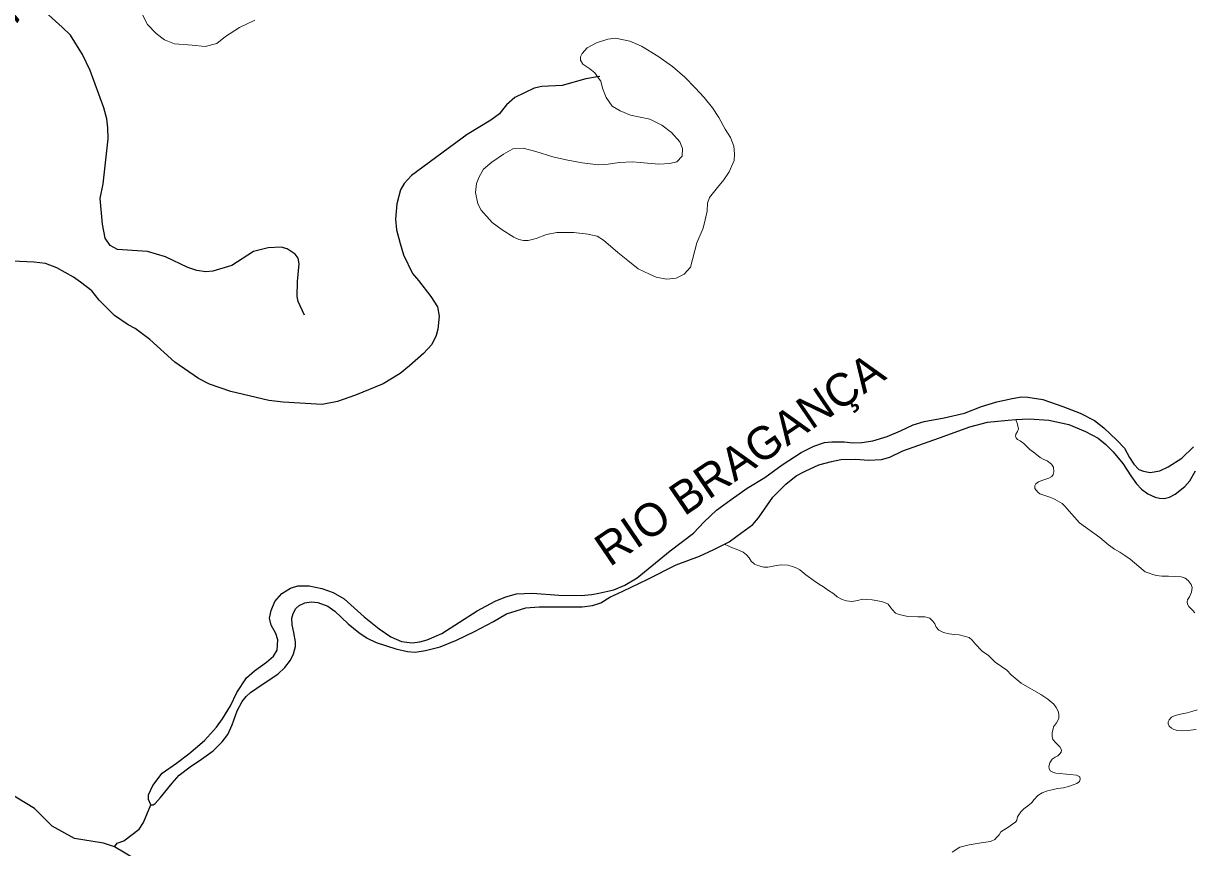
# Model space of a CAD drawing. Extents: x 267.7 to 296, y 7537.7 to 7565.8.
# Drawn here: x 278.742 to 282.305, y 7559.393 to 7561.905 of the extents above; entities that cross this region are included whole.
import ezdxf
from ezdxf.enums import TextEntityAlignment as Align

# ---------------------------------------------------------------- set-up
doc = ezdxf.new("R2010")
doc.units = 0
doc.header["$LTSCALE"] = 0.04
doc.linetypes.add('SHORT_DASHED', pattern=[2.7, 1.5, -1.2])
for name, color, linetype, lineweight in [('2', 7, 'Continuous', 25), ('21', 7, 'SHORT_DASHED', 13), ('7', 7, 'Continuous', 25)]:
    doc.layers.add(name, color=color, linetype=linetype, lineweight=lineweight)
doc.layers.add('61', color=7, linetype='Continuous')

msp = doc.modelspace()

# ---------------------------------------------------------------- linework, layer by layer
at = {"layer": '2'}
for points in [[(279.1303, 7559.5233), (279.1236, 7559.5397), (279.1236, 7559.5541), (279.1365, 7559.5828), (279.1646, 7559.6202), (279.2084, 7559.6504), (279.2458, 7559.6792), (279.294, 7559.7195), (279.3306, 7559.7597), (279.3486, 7559.7856), (279.3731, 7559.8251), (279.3925, 7559.8661), (279.422, 7559.9107), (279.4464, 7559.9323), (279.4824, 7559.9582), (279.5046, 7559.9761), (279.5154, 7559.9948), (279.5176, 7560.0265), (279.5111, 7560.0459), (279.4975, 7560.071), (279.4924, 7560.0926), (279.4967, 7560.1156), (279.5082, 7560.1429), (279.5298, 7560.1674), (279.5564, 7560.1839), (279.578, 7560.1904), (279.6132, 7560.1904), (279.6513, 7560.1832), (279.6858, 7560.1703), (279.7196, 7560.1516), (279.78, 7560.0962), (279.826, 7560.0595), (279.862, 7560.0358), (279.8943, 7560.0214), (279.9267, 7560.0171), (279.9497, 7560.02), (279.972, 7560.0265), (280.0166, 7560.0452), (280.1251, 7560.1142), (280.1791, 7560.1437), (280.2121, 7560.1573), (280.2445, 7560.1667), (280.2934, 7560.1681), (280.3732, 7560.1624), (280.4415, 7560.1616), (280.4739, 7560.1645), (280.4954, 7560.1681), (280.5407, 7560.1789), (280.5745, 7560.1926), (280.6119, 7560.2156), (280.7126, 7560.2975), (280.7838, 7560.3515), (280.8168, 7560.386), (280.8542, 7560.4219), (280.8988, 7560.4536), (280.9477, 7560.4881), (281.0016, 7560.5211), (281.0541, 7560.5592), (281.1116, 7560.5974), (281.1504, 7560.6168), (281.1835, 7560.6276), (281.2051, 7560.6297), (281.2425, 7560.6297), (281.2698, 7560.6268), (281.2964, 7560.6276), (281.3302, 7560.6326), (281.3741, 7560.6462), (281.4143, 7560.6628), (281.4531, 7560.6815), (281.4869, 7560.6915), (281.5473, 7560.7023), (281.6099, 7560.7174), (281.6617, 7560.7368), (281.7084, 7560.7512), (281.7551, 7560.7613), (281.7832, 7560.7663), (281.8026, 7560.7656), (281.8479, 7560.7584), (281.9097, 7560.7368), (281.9622, 7560.7167), (282.0061, 7560.6951), (282.0341, 7560.6721), (282.0736, 7560.6347), (282.0974, 7560.6103), (282.1125, 7560.5823), (282.1254, 7560.5614), (282.1412, 7560.5456), (282.1549, 7560.5398), (282.175, 7560.5362), (282.2052, 7560.5413), (282.2304, 7560.5535), (282.2721, 7560.5801), (282.3073, 7560.6146)], [(280.8785, 7560.3178), (280.893, 7560.3249), (280.9311, 7560.3529), (280.9642, 7560.3781), (280.9822, 7560.3982), (281.0261, 7560.4607), (281.0649, 7560.5003), (281.0972, 7560.5262), (281.1238, 7560.5406), (281.1663, 7560.56), (281.2044, 7560.57), (281.2324, 7560.5758), (281.2784, 7560.5772), (281.3173, 7560.5736), (281.3568, 7560.5758), (281.382, 7560.583), (281.4222, 7560.6017), (281.533, 7560.6419), (281.6257, 7560.675), (281.6796, 7560.6894), (281.7429, 7560.6959), (281.7662, 7560.6974)], [(281.7662, 7560.6974), (281.8069, 7560.7002), (281.8666, 7560.6959), (281.9277, 7560.6829), (281.978, 7560.6613), (282.0168, 7560.6405), (282.0406, 7560.6218), (282.0629, 7560.5988), (282.0916, 7560.5636), (282.1161, 7560.5262), (282.134, 7560.5017), (282.1491, 7560.4852), (282.1678, 7560.4715), (282.1901, 7560.4615), (282.2038, 7560.4579), (282.2182, 7560.4571), (282.234, 7560.4615), (282.252, 7560.4701), (282.2807, 7560.4938), (282.2958, 7560.5111), (282.3138, 7560.5413)], [(279.1303, 7559.5233), (279.1372, 7559.5232), (279.1437, 7559.5275), (279.1602, 7559.5462), (279.1955, 7559.59), (279.217, 7559.6138), (279.2501, 7559.6396), (279.2846, 7559.6627), (279.3206, 7559.6885), (279.3479, 7559.7151), (279.3652, 7559.7381), (279.3781, 7559.7669), (279.3939, 7559.81), (279.409, 7559.8381), (279.4205, 7559.8539), (279.4342, 7559.8661), (279.4723, 7559.892), (279.5169, 7559.9215), (279.5392, 7559.9416), (279.5564, 7559.9646), (279.565, 7559.984), (279.5708, 7560.0056), (279.5708, 7560.0207), (279.5658, 7560.0488), (279.5607, 7560.0718), (279.56, 7560.0919), (279.5643, 7560.107), (279.5722, 7560.1221), (279.5823, 7560.1307), (279.5996, 7560.1386), (279.619, 7560.1422), (279.6391, 7560.1401), (279.67, 7560.1286), (279.6909, 7560.1135), (279.7319, 7560.0754), (279.7642, 7560.0488), (279.7894, 7560.0315), (279.8167, 7560.0186), (279.8771, 7559.9984), (279.9123, 7559.9905), (279.936, 7559.9891), (279.967, 7559.9934), (280.0123, 7560.0049), (280.0619, 7560.0257), (280.1165, 7560.0516), (280.1748, 7560.0818), (280.2143, 7560.1056), (280.2438, 7560.1142), (280.2733, 7560.1235), (280.3135, 7560.1271), (280.4444, 7560.1264), (280.476, 7560.1307), (280.5019, 7560.1386), (280.5292, 7560.1559), (280.5681, 7560.1746), (280.645, 7560.2112), (280.7313, 7560.2544), (280.8017, 7560.281), (280.8456, 7560.3018), (280.8785, 7560.3178)]]:
    msp.add_lwpolyline(points, dxfattribs=at)
at = {"layer": '21'}
for points in [[(279.0976, 7561.9448), (279.12, 7561.9018), (279.1463, 7561.8737), (279.1725, 7561.855), (279.2024, 7561.8419), (279.2567, 7561.8381), (279.296, 7561.8344), (279.3316, 7561.8437), (279.3578, 7561.8643), (279.4009, 7561.8924), (279.4477, 7561.9149)], [(280.4918, 7561.7422), (280.4833, 7561.754), (280.4676, 7561.7661), (280.4471, 7561.7806), (280.4398, 7561.7927), (280.4398, 7561.8024), (280.4446, 7561.8132), (280.4603, 7561.8301), (280.4881, 7561.8459), (280.5232, 7561.8567), (280.5461, 7561.8592), (280.5896, 7561.8507), (280.6259, 7561.835), (280.6754, 7561.8048), (280.7202, 7561.7734), (280.7576, 7561.7407), (280.789, 7561.7081), (280.8168, 7561.6791), (280.8422, 7561.6477), (280.8616, 7561.6175), (280.8809, 7561.5824), (280.8966, 7561.557), (280.9063, 7561.5304), (280.9087, 7561.5075), (280.9075, 7561.4869), (280.893, 7561.4519), (280.8761, 7561.4277), (280.8567, 7561.4048), (280.8325, 7561.3746), (280.8265, 7561.3564), (280.8253, 7561.3323), (280.8193, 7561.3057), (280.8132, 7561.2803), (280.7939, 7561.2356), (280.7745, 7561.1619), (280.7552, 7561.1401), (280.731, 7561.128), (280.702, 7561.1256), (280.6706, 7561.1317), (280.6501, 7561.1401), (280.615, 7561.157), (280.5836, 7561.1824), (280.5534, 7561.2066), (280.5099, 7561.244), (280.4906, 7561.2561), (280.4616, 7561.2622), (280.4193, 7561.267), (280.3673, 7561.267), (280.3359, 7561.261), (280.3045, 7561.2489), (280.2803, 7561.2428), (280.2658, 7561.2428), (280.2513, 7561.2465), (280.2368, 7561.2537)], [(280.2368, 7561.2537), (280.2005, 7561.2755), (280.1703, 7561.2984), (280.1365, 7561.3359), (280.1268, 7561.3552), (280.1196, 7561.3891), (280.1232, 7561.4169), (280.1304, 7561.4374), (280.1437, 7561.4604), (280.1691, 7561.4821), (280.2054, 7561.5063), (280.2332, 7561.522), (280.2646, 7561.5244), (280.3032, 7561.5147), (280.3552, 7561.4978), (280.3963, 7561.4894), (280.4446, 7561.4797), (280.493, 7561.4737), (280.5244, 7561.4761), (280.5582, 7561.4809), (280.5981, 7561.4833), (280.6211, 7561.4809), (280.6779, 7561.4761), (280.7117, 7561.4773), (280.7335, 7561.4833), (280.7492, 7561.5002), (280.7504, 7561.5232), (280.7419, 7561.5437), (280.7165, 7561.5727), (280.6875, 7561.5945), (280.6513, 7561.6126), (280.5921, 7561.6247), (280.5606, 7561.638), (280.5365, 7561.6525), (280.5183, 7561.6791), (280.5063, 7561.7069), (280.5014, 7561.7286), (280.4918, 7561.7422)], [(282.2913, 7560.2074), (282.2822, 7560.2143), (282.2696, 7560.2183), (282.2313, 7560.22), (282.2113, 7560.2206), (282.1948, 7560.2223), (282.1833, 7560.2251), (282.1719, 7560.2291), (282.1605, 7560.2337), (282.1536, 7560.2388), (282.1142, 7560.272), (282.0982, 7560.2834), (282.0834, 7560.2937), (282.0668, 7560.3028), (282.0485, 7560.3159), (282.0217, 7560.3382), (281.96, 7560.3833), (281.9446, 7560.4005), (281.9286, 7560.4188), (281.916, 7560.433), (281.9069, 7560.4416), (281.8863, 7560.4536), (281.8726, 7560.4605), (281.8549, 7560.4662), (281.8395, 7560.4713), (281.8326, 7560.4765), (281.8235, 7560.4873), (281.824, 7560.4959), (281.8269, 7560.5016), (281.8355, 7560.5079), (281.8486, 7560.513), (281.8663, 7560.5187), (281.876, 7560.5244), (281.88, 7560.5296), (281.8823, 7560.5387), (281.8806, 7560.5524), (281.8743, 7560.5616), (281.8617, 7560.5719), (281.8497, 7560.577), (281.84, 7560.5821), (281.824, 7560.5947), (281.8086, 7560.6067), (281.7909, 7560.6244), (281.7795, 7560.6324), (281.7709, 7560.637), (281.7669, 7560.6415), (281.7652, 7560.6455), (281.7663, 7560.653), (281.7715, 7560.6615), (281.7738, 7560.669), (281.7732, 7560.6741), (281.7715, 7560.681), (281.7709, 7560.6838), (281.7662, 7560.6974)], [(281.9312, 7559.6155), (281.888, 7559.6202), (281.879, 7559.6226), (281.8705, 7559.6274), (281.8672, 7559.634), (281.8667, 7559.6406), (281.87, 7559.652), (281.8767, 7559.6624), (281.8861, 7559.6691), (281.8937, 7559.6729), (281.9004, 7559.6785), (281.9042, 7559.6842), (281.9051, 7559.6909), (281.9004, 7559.7003), (281.8876, 7559.7122), (281.879, 7559.7226), (281.8771, 7559.7321), (281.8771, 7559.7435), (281.8795, 7559.7549), (281.8809, 7559.761), (281.8904, 7559.7733), (281.8966, 7559.7866), (281.8975, 7559.7956), (281.8961, 7559.807), (281.889, 7559.8203), (281.8814, 7559.8302), (281.8634, 7559.8459), (281.8425, 7559.8601), (281.7819, 7559.8942), (281.7515, 7559.9198), (281.7383, 7559.934), (281.7027, 7559.9587), (281.6828, 7559.9781), (281.6638, 7559.9914), (281.643, 7560.0132), (281.6335, 7560.025), (281.6236, 7560.0331), (281.5932, 7560.0416), (281.5795, 7560.043), (281.5634, 7560.0445), (281.5458, 7560.0483), (281.5311, 7560.0558), (281.5231, 7560.0644), (281.5188, 7560.0753), (281.5131, 7560.0833), (281.5036, 7560.0919), (281.4889, 7560.0961), (281.4671, 7560.0961), (281.4373, 7560.0971), (281.4103, 7560.1032), (281.3989, 7560.108), (281.3899, 7560.1175), (281.3851, 7560.1241), (281.3775, 7560.1345), (281.3709, 7560.1383), (281.3572, 7560.1435), (281.3287, 7560.1483), (281.3121, 7560.1497), (281.2979, 7560.1502), (281.2846, 7560.1464), (281.2666, 7560.1435), (281.25, 7560.1454), (281.2372, 7560.1492), (281.2221, 7560.1578), (281.2116, 7560.1668), (281.1927, 7560.1791), (281.1804, 7560.1881), (281.168, 7560.1952), (281.1519, 7560.2061), (281.1259, 7560.2241), (281.1083, 7560.2393), (281.0984, 7560.2445), (281.086, 7560.2497), (281.0713, 7560.254), (281.0519, 7560.2545), (281.0363, 7560.2526), (281.023, 7560.2497), (281.0107, 7560.2478), (280.9983, 7560.2478), (280.9799, 7560.2526), (280.9699, 7560.2573), (280.96, 7560.2663), (280.9533, 7560.2763), (280.9457, 7560.2848), (280.9353, 7560.2933), (280.9187, 7560.3009), (280.9031, 7560.3071), (280.8917, 7560.3118), (280.8785, 7560.3178)], [(282.2896, 7560.148), (282.2953, 7560.1577), (282.301, 7560.1714), (282.3033, 7560.1857), (282.3004, 7560.1954), (282.2913, 7560.2074)], [(282.3113, 7560.1086), (282.3044, 7560.1166), (282.2936, 7560.1274), (282.2896, 7560.1349), (282.2884, 7560.1417), (282.2896, 7560.148)], [(282.3159, 7559.7527), (282.289, 7559.7499), (282.2702, 7559.7493), (282.2582, 7559.7504), (282.2473, 7559.7527), (282.2405, 7559.7573), (282.233, 7559.7636), (282.2307, 7559.7699), (282.2307, 7559.7767), (282.233, 7559.783), (282.2405, 7559.7904), (282.2513, 7559.7961), (282.2673, 7559.8001), (282.2879, 7559.8036), (282.3027, 7559.8076), (282.3187, 7559.8133)], [(281.952, 7559.5885), (281.9601, 7559.5951), (281.9625, 7559.6022), (281.9606, 7559.6084), (281.9511, 7559.6136), (281.9312, 7559.6155)], [(281.5724, 7559.3794), (281.5956, 7559.3941), (281.624, 7559.4017), (281.6605, 7559.4074), (281.6885, 7559.4122), (281.7018, 7559.4178), (281.7084, 7559.425), (281.715, 7559.4325), (281.7207, 7559.4415), (281.7444, 7559.4562), (281.7572, 7559.4657), (281.7653, 7559.4709), (281.7691, 7559.4766), (281.7714, 7559.487), (281.7814, 7559.5017), (281.7909, 7559.5112), (281.806, 7559.5226), (281.815, 7559.5302), (281.8217, 7559.5397), (281.8331, 7559.552), (281.8459, 7559.56), (281.8624, 7559.5657), (281.8805, 7559.5705), (281.8933, 7559.5728), (281.9108, 7559.5752), (281.9269, 7559.579), (281.9411, 7559.5842), (281.952, 7559.5885)]]:
    msp.add_lwpolyline(points, dxfattribs=at)
at = {"layer": '7'}
msp.add_line((280.4984, 7561.7433), (280.4918, 7561.7422), dxfattribs=at)
for points in [[(279.5991, 7561.0156), (279.5797, 7561.0573), (279.576, 7561.0725), (279.577, 7561.1179), (279.5827, 7561.1724), (279.5791, 7561.1897), (279.5698, 7561.201), (279.5462, 7561.2174), (279.5277, 7561.2231), (279.4879, 7561.2203), (279.4434, 7561.2092), (279.3774, 7561.1665), (279.3191, 7561.1498), (279.2979, 7561.1479), (279.2706, 7561.152), (279.2428, 7561.1612), (279.1747, 7561.1936), (279.1207, 7561.2096), (279.029, 7561.2157), (279.0066, 7561.228), (278.9911, 7561.2506), (278.9827, 7561.2925), (278.9765, 7561.3709), (278.9852, 7561.4157), (279.0001, 7561.5528), (278.9995, 7561.5863), (278.9961, 7561.6136), (278.9876, 7561.6476), (278.9454, 7561.7613), (278.9221, 7561.81), (278.8988, 7561.8474), (278.8852, 7561.8692), (278.8606, 7561.8928), (278.7877, 7561.9585)], [(280.4918, 7561.7422), (280.4563, 7561.7361), (280.3841, 7561.7156), (280.3216, 7561.7124), (280.2987, 7561.707), (280.2396, 7561.6793), (280.2139, 7561.6565), (280.1981, 7561.6363), (280.1927, 7561.6294), (280.1661, 7561.6096), (280.0941, 7561.5665), (279.925, 7561.4412), (279.9027, 7561.4165), (279.891, 7561.3979), (279.8798, 7561.355), (279.8764, 7561.3083), (279.8791, 7561.276), (279.8899, 7561.2339), (279.9003, 7561.199), (279.9273, 7561.1428), (279.9455, 7561.1209), (279.9835, 7561.0727), (280.0034, 7561.0406), (280.009, 7561.0124), (280.0044, 7560.9731), (279.9999, 7560.9536), (279.987, 7560.9265), (279.9613, 7560.8992), (279.9188, 7560.8613), (279.8905, 7560.8383), (279.8388, 7560.8067), (279.7541, 7560.7714), (279.699, 7560.7521), (279.6526, 7560.7434), (279.5339, 7560.7504), (279.4899, 7560.7554), (279.374, 7560.7832), (279.309, 7560.8058), (279.2759, 7560.823), (279.2036, 7560.872), (279.1269, 7560.9416), (279.0825, 7560.9751), (279.0609, 7560.9865), (279.02, 7561.015), (278.9725, 7561.0614), (278.9509, 7561.0902), (278.9159, 7561.1158), (278.8943, 7561.1316), (278.8439, 7561.1596), (278.8091, 7561.1733), (278.7754, 7561.1774), (278.7077, 7561.1805)], [(279.0197, 7559.3957), (278.986, 7559.4067), (278.8983, 7559.4211), (278.8297, 7559.4588), (278.7755, 7559.5121), (278.6911, 7559.5638), (278.6618, 7559.569), (278.5798, 7559.5655), (278.5291, 7559.5739), (278.4269, 7559.6037), (278.4084, 7559.6023), (278.3367, 7559.5866), (278.3027, 7559.584), (278.2797, 7559.5893), (278.2467, 7559.6021), (278.2269, 7559.6181), (278.1943, 7559.656), (278.1739, 7559.6878), (278.1408, 7559.7218), (278.1175, 7559.736), (278.0936, 7559.7456), (278.0554, 7559.761)], [(279.0197, 7559.3957), (279.0283, 7559.4063), (279.0486, 7559.4137), (279.0944, 7559.4493), (279.1078, 7559.4692), (279.1303, 7559.5233)], [(279.9209, 7559.1985), (279.8809, 7559.2335), (279.8675, 7559.2457), (279.85, 7559.2498), (279.8264, 7559.251), (279.7904, 7559.2515), (279.732, 7559.2652), (279.6934, 7559.2707), (279.6738, 7559.277), (279.6159, 7559.3071), (279.5955, 7559.3155), (279.5768, 7559.3193), (279.5529, 7559.3205), (279.4811, 7559.3119), (279.3697, 7559.3148), (279.3354, 7559.3252), (279.3165, 7559.3363), (279.285, 7559.3443), (279.2495, 7559.3417), (279.2063, 7559.3316), (279.139, 7559.3338), (279.0897, 7559.3542), (279.0197, 7559.3957)]]:
    msp.add_lwpolyline(points, dxfattribs=at)

# ---------------------------------------------------------------- texts
at = {"layer": '61'}
for s, rotation, p in [('RIO CARAPEBA OU CANAL DA  ANDREZA', 59.138, (279.2153, 7562.7274)), ('RIO BRAGANÇA', 34.216, (280.9522, 7560.5353))]:
    msp.add_text(s, height=0.1, rotation=rotation, dxfattribs=at).set_placement(p, align=Align.CENTER)

doc.saveas('drawing.dxf')
